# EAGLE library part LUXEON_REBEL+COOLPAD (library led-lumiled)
LUXEON REBEL LED with cooling pads Display Layer Refence in Board for more information Stop and Cream Mask defined by Luxeon Rebel Footprint _customer.dxf
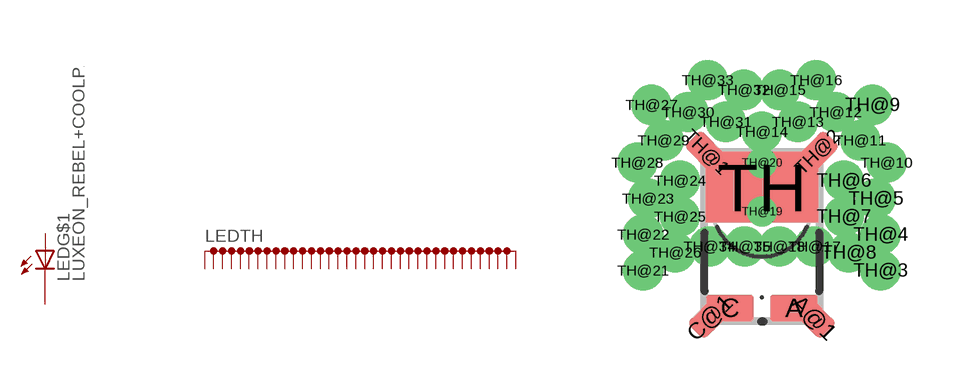
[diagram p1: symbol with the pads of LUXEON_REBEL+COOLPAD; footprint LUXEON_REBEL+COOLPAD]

Designator prefix LED; gates TH=LUXEON_THERMAL36 G$1=LED-A2C2

## LUXEON_REBEL+COOLPAD (OC_FARNELL: unknown; OC_NEWARK: unknown)  [LUXEON_REBEL+COOLPAD]
A  G$1:A  pas
A@1  G$1:A  pas
C  G$1:C  pas
C@1  G$1:C  pas
TH  TH:TH  pwr
TH@1  TH:TH  pwr
TH@2  TH:TH  pwr
TH@3  TH:TH  pwr
TH@4  TH:TH  pwr
TH@5  TH:TH  pwr
TH@6  TH:TH  pwr
TH@7  TH:TH  pwr
TH@8  TH:TH  pwr
TH@9  TH:TH  pwr
TH@10  TH:TH  pwr
TH@11  TH:TH  pwr
TH@12  TH:TH  pwr
TH@13  TH:TH  pwr
TH@14  TH:TH  pwr
TH@15  TH:TH  pwr
TH@16  TH:TH  pwr
TH@17  TH:TH  pwr
TH@18  TH:TH  pwr
TH@19  TH:TH  pwr
TH@20  TH:TH  pwr
TH@21  TH:TH  pwr
TH@22  TH:TH  pwr
TH@23  TH:TH  pwr
TH@24  TH:TH  pwr
TH@25  TH:TH  pwr
TH@26  TH:TH  pwr
TH@27  TH:TH  pwr
TH@28  TH:TH  pwr
TH@29  TH:TH  pwr
TH@30  TH:TH  pwr
TH@31  TH:TH  pwr
TH@32  TH:TH  pwr
TH@33  TH:TH  pwr
TH@34  TH:TH  pwr
TH@35  TH:TH  pwr

## Footprint LUXEON_REBEL+COOLPAD (pad centres in mm)
LUXEON REBEL LED with cooling pads Please read also description in Layer 49 Reference. Stop and Cream Mask defined by Footprint Rebel customer_070207.dxf
smd 1.2 x 0.67: A 0.8,-2.51; C -0.8,-2.51
smd 1 x 0.6 rotated 315: A@1 1.31,-2.75
smd 1 x 0.6 rotated 225: C@1 -1.31,-2.75
smd 2.8 x 1.77: TH 0,0.51
smd 1 x 0.6 rotated 135: TH@1 -1.39,1.39
smd 1 x 0.6 rotated 45: TH@2 1.39,1.39
drill 0.5 pad 0.6 round: TH@3 2.971,-1.57; TH@4 2.971,-0.67; TH@5 2.85,0.23; TH@6 2.05,0.68; TH@7 2.05,-0.22; TH@8 2.171,-1.12; TH@9 2.764,2.575; TH@10 3.116,1.13; TH@11 2.461,1.687; TH@12 1.844,2.394; TH@13 0.9,2.15; TH@14 0,1.9; TH@15 0.45,2.95; TH@16 1.356,3.196; TH@17 1.31,-0.97; TH@18 0.43,-0.97; TH@21 -2.971,-1.57; TH@22 -2.971,-0.67; TH@23 -2.85,0.23; TH@24 -2.05,0.68; TH@25 -2.05,-0.22; TH@26 -2.171,-1.12; TH@27 -2.764,2.575; TH@28 -3.116,1.13; TH@29 -2.461,1.687; TH@30 -1.844,2.394; TH@31 -0.9,2.15; TH@32 -0.45,2.95; TH@33 -1.356,3.196; TH@34 -1.31,-0.97; TH@35 -0.43,-0.97
drill 0.25 pad 0.4 round: TH@19 0,-0.095; TH@20 0,1.125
